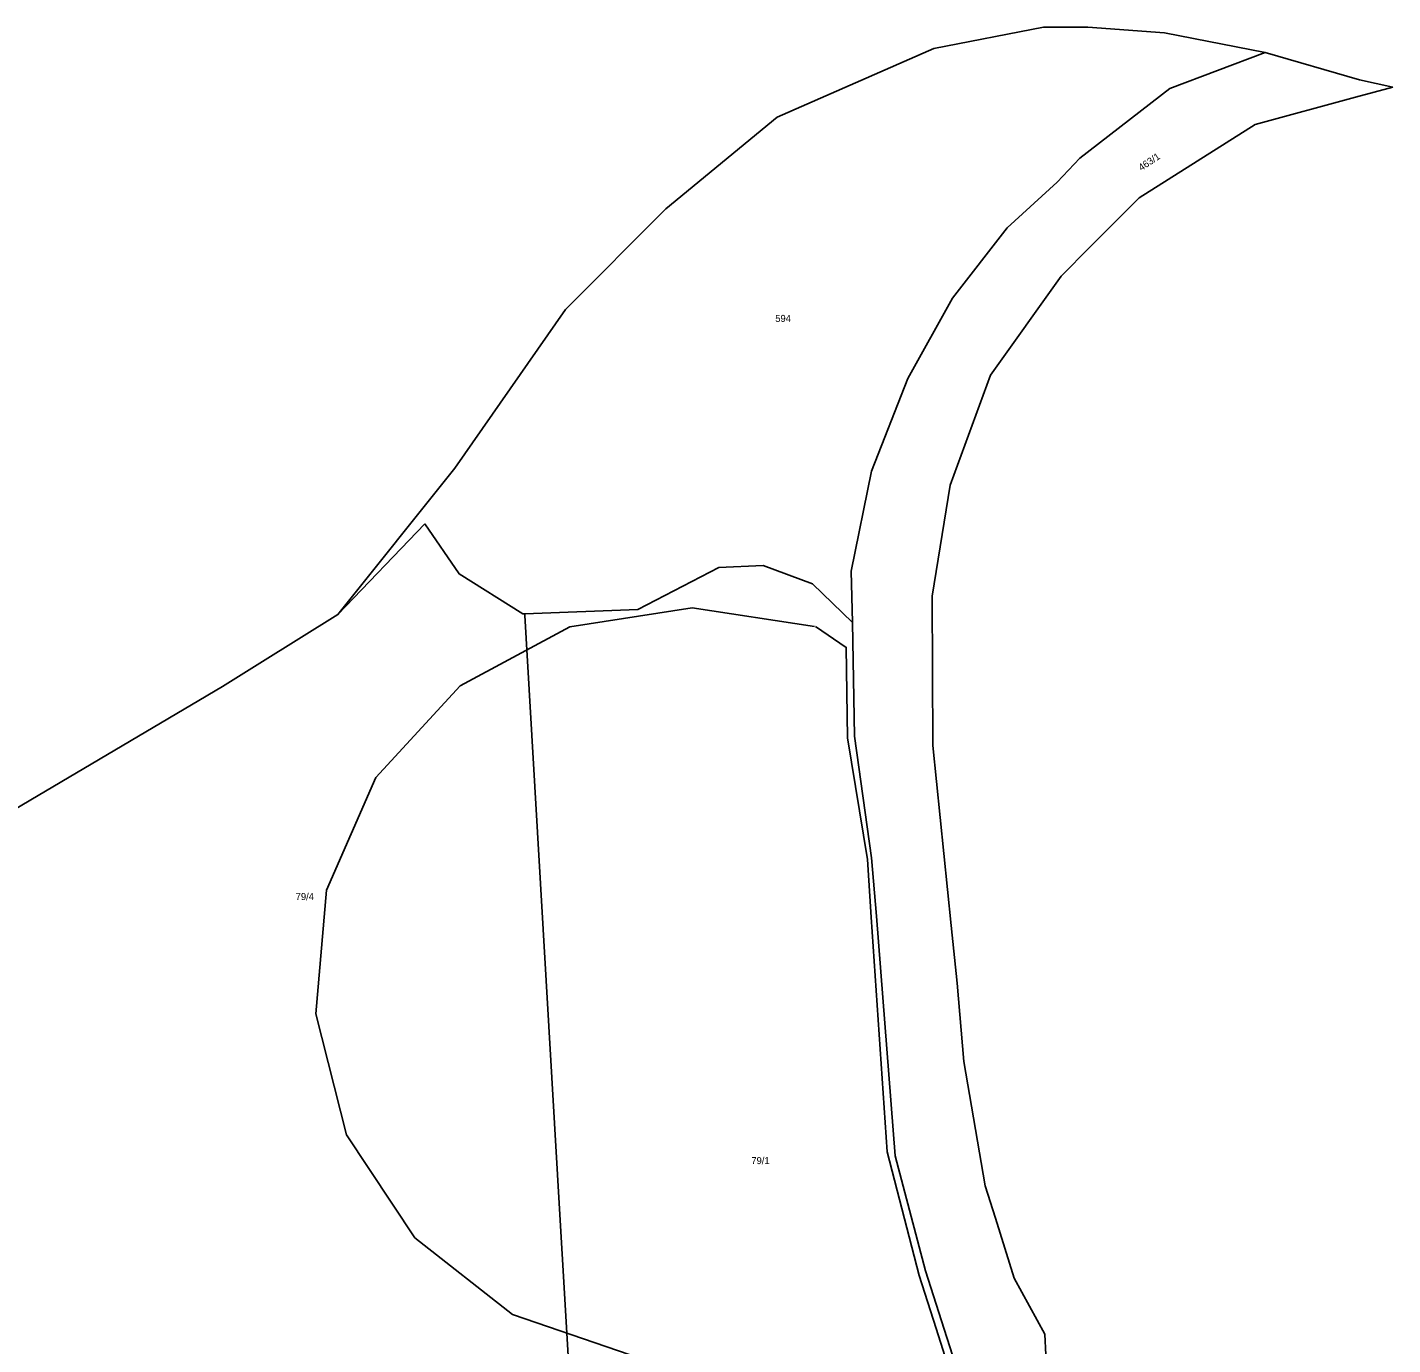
# Model space of a CAD drawing. Extents: x -882150 to -879379, y -1022570 to -1019819.
# Drawn here: x -879708.9 to -879378.6, y -1020137.6 to -1019818.8 of the extents above; entities that cross this region are included whole.
import ezdxf

# ---------------------------------------------------------------- set-up
doc = ezdxf.new("R2010")
doc.units = 0
for name, color, linetype in [('Hranice parcel', 7, 'Continuous'), ('Parcelní čísla', 7, 'Continuous'), ('Vnitřní kresba', 7, 'Continuous')]:
    doc.layers.add(name, color=color, linetype=linetype)

msp = doc.modelspace()

# ---------------------------------------------------------------- linework, layer by layer
at = {"layer": 'Hranice parcel'}
for p, q in [((-879489.59, -1019823.95), (-879463.11, -1019818.83)), ((-879463.11, -1019818.83), (-879452.32, -1019818.83)), ((-879612.72, -1019938.99), (-879633.8, -1019960.95)), ((-879474.71, -1020107), (-879477.19, -1020099.14)), ((-879461.84, -1020153.53), (-879462.72, -1020135.04))]:
    msp.add_line(p, q, dxfattribs=at)
for points in [[(-879452.32, -1019818.83), (-879433.77, -1019820.18), (-879409.47, -1019824.9)], [(-879633.8, -1019960.95), (-879605.52, -1019925.48), (-879578.68, -1019887.14), (-879554.42, -1019862.78), (-879527.48, -1019840.56), (-879489.59, -1019823.95)], [(-879409.47, -1019824.9), (-879432.5, -1019833.6), (-879454.26, -1019850.52), (-879459.75, -1019856.27), (-879471.87, -1019867.37), (-879485.1, -1019884.37), (-879495.86, -1019903.83), (-879504.69, -1019926.2), (-879509.59, -1019950.43), (-879509.31, -1019962.82)], [(-879409.47, -1019824.9), (-879386.66, -1019831.54), (-879378.59, -1019833.34)], [(-879451.81, -1019871.97), (-879439.91, -1019860.11), (-879411.86, -1019842.35), (-879387.56, -1019835.72), (-879378.59, -1019833.34)], [(-879485.4, -1020036.21), (-879489.83, -1019992.59), (-879489.99, -1019956.5), (-879485.67, -1019929.59), (-879475.91, -1019903), (-879458.78, -1019879.01), (-879451.81, -1019871.97)], [(-879588.59, -1019960.72), (-879589.05, -1019960.74), (-879604.46, -1019951.08), (-879612.72, -1019938.99)], [(-879509.31, -1019962.82), (-879518.94, -1019953.46), (-879530.93, -1019949.04), (-879541.64, -1019949.54), (-879561.24, -1019959.73), (-879588.59, -1019960.72)], [(-879730.66, -1020019.05), (-879661.73, -1019978.33), (-879652.67, -1019972.68), (-879633.8, -1019960.95)], [(-879677.18, -1020472.46), (-879667.75, -1020437.8), (-879665.81, -1020409.01), (-879666.61, -1020374.63), (-879663.82, -1020356.18), (-879654.07, -1020337.43), (-879631.48, -1020317.07), (-879614.53, -1020309.6), (-879594.85, -1020302.07), (-879558.14, -1020284.55), (-879531.56, -1020266.67), (-879502.78, -1020237.58), (-879486.9, -1020212.69), (-879479.67, -1020182.61), (-879481.19, -1020152.24), (-879491.62, -1020119.75), (-879498.99, -1020091.88), (-879503.51, -1020033.88), (-879504.65, -1020019.83), (-879508.77, -1019990.39), (-879509.31, -1019962.82)], [(-879588.59, -1019960.72), (-879588.56, -1019961.2), (-879580.3, -1020101.99), (-879572.03, -1020242.79), (-879635.31, -1020244.96)], [(-879477.19, -1020099.14), (-879482.33, -1020069.11), (-879483.98, -1020050.13), (-879485.4, -1020036.21)], [(-879462.72, -1020135.04), (-879470.14, -1020121.51), (-879474.71, -1020107)]]:
    msp.add_lwpolyline(points, dxfattribs=at)
at = {"layer": 'Vnitřní kresba'}
msp.add_line((-879548.1, -1019959.3), (-879518.44, -1019963.86), dxfattribs=at)
for points in [[(-879548.1, -1019959.3), (-879577.68, -1019963.91), (-879604.17, -1019978.16), (-879624.6, -1020000.35), (-879636.57, -1020027.66), (-879639.14, -1020057.51), (-879631.73, -1020086.8), (-879615.2, -1020111.72), (-879591.51, -1020130.32), (-879563.07, -1020140.04), (-879550.31, -1020140.04), (-879566.18, -1020147.67), (-879588.25, -1020168.06), (-879603.19, -1020193.89), (-879610.24, -1020223.02), (-879607.79, -1020253.06), (-879596.91, -1020280.95)], [(-879518.25, -1019963.85), (-879510.79, -1019968.87), (-879510.53, -1019990.75), (-879505.64, -1020020.23), (-879504.74, -1020034.13), (-879500.88, -1020090.97), (-879493.16, -1020120.83), (-879489.04, -1020133.7), (-879483.12, -1020152.24), (-879483.12, -1020181.98), (-879489.3, -1020209.27), (-879505.25, -1020235.02), (-879532.28, -1020264.56)]]:
    msp.add_lwpolyline(points, dxfattribs=at)

# ---------------------------------------------------------------- texts
at = {"layer": 'Parcelní čísla'}
msp.add_text('463/1', height=1.7, rotation=34, dxfattribs=at).set_placement((-879439.384, -1019853.664))
for s, p in [('594', (-879527.97, -1019890.12)), ('79/4', (-879644, -1020030.02)), ('79/1', (-879533.75, -1020093.91))]:
    msp.add_text(s, height=1.7, dxfattribs=at).set_placement(p)

doc.saveas('drawing.dxf')
